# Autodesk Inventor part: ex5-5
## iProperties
Shininess: 64.0
Length Units: 11269
Angle Units: 11279
Time Units: 11290
Mass Units: 11283
Length Display Precision: 3
Angle Display Precision: 2
Compacted: True
Part Number: ex5-5
Document SubType Name: Modeling
Created: 2003-11
Cost Center: 0 kg
Designer: Elise Moss
Authority: 11426.17 mm^3
Manufacturer: Standard
Standards Organization: Custom
Density: 0.0
Volumn: 0.0
Area: 0.0
PropertySet Name: Model Information
Control State: 0
Master: False
Checked Out: False
SaveDate: 2003-11-13
SaveTime: 15:42
TotalMass: 0 kg
TotalVolume: 11426.17 mm^3
Author: Elise Moss
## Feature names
1. Extrusion1
2. Hole1
3. Shell3
